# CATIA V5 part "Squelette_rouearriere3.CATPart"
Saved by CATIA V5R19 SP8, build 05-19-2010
Part number: Squelette_roue_arrière3
Bounding box of the stored display mesh (mm): x 50 to 70, y 50 to 80, z 50 to 50
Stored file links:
  G:\EU_thinkMotion\CFAO_2010\MMS_groupe2\MMS_groupe2\A reprendre\jcauchy\Squelette_rouearriere3.CATPart
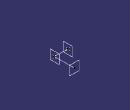
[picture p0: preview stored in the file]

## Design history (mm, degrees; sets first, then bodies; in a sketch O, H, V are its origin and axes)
Parameters
  Longueurfixation_rouearriere3 = 20 mm
  Rayonroue_rouearriere3 = 30 mm
Set1
  Point1: (50, 50, 50)
  Point2: (70 {= 50mm+Longueurfixation_rouearriere3}, 50, 50)
  Line1: type PtPt, FirstPoint Point1, SecondPoint Point2
  Plane1: type Normal, Curve Line1, RefPoint Point1
  Plane2: type Normal, Curve Line1, RefPoint Point2
  Point3: type OnCurve, Support Line1, Length 20 {= Longueurfixation_rouearriere3}
  Line2: type Angle, RefPoint Point3, Curve Line1, Support xy-plane, Start 0, End 30 {= Rayonroue_rouearriere3}, Angle 90
  Plane3: type Normal, Curve Line2, RefPoint vertex of Line2
Body1 (main body)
